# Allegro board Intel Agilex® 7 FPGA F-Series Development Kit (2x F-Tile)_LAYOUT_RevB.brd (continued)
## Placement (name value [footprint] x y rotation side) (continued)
C1024  0.1uF  [0402]  10.93 31.7 270 bottom
C1025  0.1uF  [0402]  5.6 31.7 270 bottom
C1026  0.1uF  [0402]  59.76 96.47 90 bottom
C1027  0.1uF  [0402]  61.09 57.48 180 top
C1028  0.1uF  [0402]  60.08 57.48 180 top
C1029  0.1uF  [0402]  63.13 57.48 180 top
C1030  0.1uF  [0402]  62.11 57.48 180 top
C1031  0.1uF  [0402]  68.08 39.64 180 top
C1032  100uF  [0805]  115.2 87.33 90 top
C1033  100uF  [0805]  122.05 87.33 90 top
C1034  100uF  [0805]  86.44 87.33 90 top
C1035  100uF  [0805]  125.99 87.33 90 top
C1036  100uF  [0805]  120.63 36.02 0 top
C1037  100uF  [0805]  114.94 36.02 0 top
C1038  47uF  [0603]  132.98 75.77 0 top
C1039  47uF  [0603]  133.36 56.09 0 top
C1040  47uF  [0603]  133.36 64.72 0 top
C1041  47uF  [0603]  133.36 44.53 0 top
C1042  10uF  [0402]  107.73 53.41 120 bottom
C1043  10uF  [0402]  107.7 51.55 120 bottom
C1044  22uF  [0603]  117.91 36.09 90 top
C1045  47uF  [0805]  70.11 70.18 270 top
C1046  47uF  [0805]  70.11 72.34 270 top
C1047  1uF  [0201]  94.1 71.3 210 bottom
C1048  1uF  [0201]  94.1 70.38 210 bottom
C1049  4.7uF  [0402]  104.02 71.14 0 bottom
C1050  4.7uF  [0402]  90.56 67.96 180 bottom
C1051  4.7uF  [0402]  89.54 72.69 60 bottom
C1052  4.7uF  [0402]  111.61 54.86 320 bottom
C1053  4.7uF  [0402]  111.46 53.15 180 bottom
C1054  4.7uF  [0402]  96.58 71.81 120 bottom
C1055  4.7uF  [0402]  96.58 70.89 120 bottom
C1056  4.7uF  [0402]  98.17 72.29 60 bottom
C1057  4.7uF  [0402]  108.55 71.37 300 bottom
C1058  4.7uF  [0402]  106.96 71.37 300 bottom
C1059  4.7uF  [0402]  105.34 71.49 300 bottom
C1060  4.7uF  [0402]  98.17 71.37 60 bottom
C1061  4.7uF  [0402]  92.64 69.99 240 bottom
C1062  4.7uF  [0402]  106.93 52.03 300 bottom
C1063  4.7uF  [0402]  94.21 52.97 300 bottom
C1064  4.7uF  [0402]  94.98 52.49 120 bottom
C1065  4.7uF  [0402]  93.39 51.57 120 bottom
C1066  4.7uF  [0402]  104.54 51.57 120 bottom
C1067  4.7uF  [0402]  104.54 52.49 120 bottom
C1068  4.7uF  [0402]  106.14 52.49 120 bottom
C1069  4.7uF  [0402]  94.98 51.57 120 bottom
C1070  10uF  [0402]  87.92 66.81 120 bottom
C1071  10uF  [0402]  85.34 67.16 300 bottom
C1072  1uF  [0201]  87.84 64.93 30 bottom
C1073  4.7uF  [0402]  113.72 59.15 180 bottom
C1074  47uF  [0805]  127.64 59.51 270 top
C1075  47uF  [0805]  127.64 65.74 270 top
C1076  47uF  [0805]  73.92 65.36 90 top
C1077  47uF  [0805]  70.11 60.53 90 top
C1078  47uF  [0805]  73.92 67.77 90 top
C1079  47uF  [0805]  82.71 87.33 270 top
C1080  0.1uF  [0402]  55.38 90.63 90 bottom
C1081  0.1uF  [0402]  53.47 87.45 0 bottom
C1082  2.2uF  [0402]  50.3 89.11 0 bottom
C1084  22uF  [1206]  42.81 84.91 90 top
C1085  22uF  [1206]  57.79 84.91 270 top
C1086  22uF  [1206]  40.27 84.91 90 top
C1087  22uF  [1206]  60.33 84.91 270 top
C1091  150uF  [2917_2MM]  42.81 81.1 270 bottom
C1092  4.7uF  [0603]  55.13 89.36 180 bottom
C1093  0.1uF, DNI  [0402]  198.13 59.01 0 bottom
C1096  22uF  [1206]  198 49.35 180 bottom
C1097  22uF  [1206]  198 46.81 180 top
C1098  1uF  [0402]  197.87 49.94 90 top
C1099  22uF  [1206]  193.17 49.35 0 bottom
C1100  22uF  [1206]  193.17 49.35 0 top
C1101  22uF  [1206]  193.17 46.81 0 bottom
C1102  22uF  [1206]  193.17 46.81 0 top
C1103  10nF  [0402]  194.32 59.01 180 bottom
C1105  100uF  [1206]  192.67 36.02 90 top
C1106  100uF  [1206]  192.67 36.02 90 bottom
C1107  100uF  [1206]  185.43 36.02 90 bottom
C1110  100uF  [1206]  170.31 35.89 90 bottom
C1111  100uF  [1206]  170.31 35.89 90 top
C1112  100uF  [1206]  175.14 35.89 90 bottom
C1115  22uF  [1206]  187.97 22.18 0 bottom
C1116  22uF  [1206]  187.97 19.51 0 top
C1117  22uF  [1206]  175.01 19.51 180 top
C1118  22uF  [1206]  175.01 22.18 180 bottom
C1120  1uF  [0402]  187.97 21.29 270 top
C1121  1uF  [0402]  175.01 21.29 90 top
C1122  100uF  [2917_4P3MM]  194.57 24.59 90 top
C1123  4.7uF  [0402]  179.65 30.69 90 bottom
C1124  10nF  [0402]  180.86 34.5 90 bottom
C1125  DNI  [0402]  183.27 35.77 90 bottom
C1126  220pF  [0402]  178.95 35 0 bottom
C1127  1uF  [0402]  50.76 87.71 270 bottom
C1128  47uF, DNI  [1206]  58.94 73.48 180 bottom
C1129  47uF, DNI  [1206]  53.73 73.48 0 bottom
C1132  100uF  [1206]  58.94 68.15 180 top
C1133  100uF  [1206]  58.94 70.94 180 top
C1134  100uF  [1206]  53.73 68.15 0 top
C1135  100uF  [1206]  53.73 70.94 0 top
C1136  470uF  [2917]  55.76 69.42 180 bottom
C1138  47uF, DNI  [1206]  47.89 73.48 180 bottom
C1139  47uF, DNI  [1206]  41.92 73.48 0 bottom
C1142  100uF  [1206]  42.17 68.15 0 top
C1143  100uF  [1206]  48.39 68.15 180 top
C1144  100uF  [1206]  42.17 70.94 0 top
C1145  100uF  [1206]  48.39 70.94 180 top
C1146  470uF  [2917]  46.24 69.42 0 bottom
C1149  2.2nF  [0402]  51.19 89.11 0 bottom
C1154  4.7uF  [0603]  197.11 72.98 90 bottom
C1156  2.2uF  [0402]  196.86 77.8 270 bottom
C1157  1uF  [0402]  195.46 77.35 180 bottom
C1158  0.1uF  [0402]  198.38 72.72 0 bottom
C1159  22uF  [1206]  192.67 85.3 0 top
C1160  22uF  [1206]  192.67 87.84 0 top
C1161  22uF  [1206]  194.19 67.77 180 top
C1162  22uF  [1206]  194.19 70.31 180 top
C1164  1uF  [0402]  192.41 76.53 0 bottom
C1165  1uF  [0402]  192.41 80.6 0 bottom
C1166  47uF, DNI  [1206]  171.71 68.28 90 top
C1167  47uF, DNI  [1206]  171.71 74.37 270 top
C1170  100uF  [1206]  174.38 68.28 90 top
C1171  100uF  [1206]  176.92 68.28 90 top
C1172  100uF  [1206]  174.38 74.37 270 top
C1173  100uF  [1206]  176.92 74.37 270 top
C1174  470uF  [2917]  179.08 71.96 0 bottom
C1176  150uF  [2917_2MM]  188.86 85.68 180 bottom
C1178  22pF  [0402]  200.16 76.15 270 bottom
C1179  2.2nF  [0402]  198.46 76.15 90 bottom
C1180  0.1uF  [0402]  195.21 74.63 270 bottom
C1181  47uF, DNI  [1206]  171.71 79.71 90 top
C1182  47uF, DNI  [1206]  171.71 87.45 270 top
C1185  100uF  [1206]  174.38 87.45 270 top
C1186  100uF  [1206]  174.38 79.71 90 top
C1187  100uF  [1206]  176.92 87.45 270 top
C1188  100uF  [1206]  176.92 79.71 90 top
C1189  470uF  [2917]  179.08 85.68 0 bottom
C1191  22pF  [0402]  196.86 78.69 270 bottom
C1193  2.2nF  [0402]  196.86 76.91 270 bottom
C1194  0.1uF  [0402]  66.05 39.64 180 top
C1195  10nF  [0402]  69.1 39.7 180 top
C1196  10nF  [0402]  67.06 39.64 180 top
C1197  10uF  [0402]  64.9 39.64 0 top
C1198  47uF  [0603]  63.51 37.8 180 top
C1199  1nF, DNI  [0402]  73.67 44.15 180 bottom
C1200  DNI  [0402]  193.05 58.94 0 bottom
C1201  DNI  [0402]  189.87 56.66 0 top
C1202  100pf  [0402]  189.87 54.88 180 top
C1203  0.1uF  [0402]  197.43 54.69 90 bottom
C1204  2.2uF  [0402]  198.13 52.91 0 bottom
C1205  0.1uF  [0402]  51.57 84.66 90 bottom
C1206  0.1uF  [0402]  47.51 84.66 90 bottom
C1207  2.2uF  [0402]  47.76 87.45 180 bottom
C1208  4.7uF  [0603]  55.89 86.95 270 bottom
C1209  22pF  [0402]  51.95 92.41 0 bottom
C1210  22pF  [0402]  49.41 89.11 0 bottom
C1211  2.2nF  [0402]  51.95 90.71 180 bottom
C1212  220nF  [0402]  51.06 91.51 0 bottom
C1213  220nF  [0402]  52.84 91.52 180 bottom
C1214  220nF  [0402]  199.26 77.04 270 bottom
C1215  220nF  [0402]  199.27 75.26 90 bottom
C1216  4.7uF  [0603]  194.7 72.21 180 bottom
C1217  2.2uF  [0402]  195.21 80.34 90 bottom
C1218  1uF, DNI  [0402]  180.6 29.8 315 bottom
C1219  1uF  [0402]  180.09 59.51 180 top
C1220  10nF  [0402]  58.3 77.17 90 top
C1221  10nF  [0402]  42.3 77.17 90 top
C1222  10nF  [0402]  184.54 70.82 0 top
C1223  10nF  [0402]  183.4 86.69 0 top
C1224  1uF  [0201]  97.42 57.89 0 bottom
C1225  0.1uF  [0402]  85.35 17.6 270 bottom
C1226  0.1uF  [0402]  85.35 15.19 270 bottom
C1227  0.1uF  [0402]  71.38 20.53 0 bottom
C1228  0.1uF  [0402]  85.35 19.89 270 bottom
C1229  0.1uF  [0402]  81.16 13.29 180 bottom
C1230  0.1uF  [0402]  79.89 13.29 180 bottom
C1231  0.1uF  [0402]  78.62 13.29 180 bottom
C1232  0.1uF  [0402]  77.35 13.29 180 bottom
C1233  0.1uF  [0402]  70.87 13.29 180 bottom
C1234  0.1uF  [0402]  75.45 13.29 180 bottom
C1235  0.1uF  [0402]  72.4 13.29 180 bottom
C1236  0.1uF  [0402]  71.38 22.94 0 bottom
C1237  0.1uF  [0402]  91.87 69.51 60 bottom
C1238  100uF  [1206]  130.18 77.68 180 bottom
C1239  100uF  [1206]  130.18 69.93 180 bottom
C1240  100uF  [1206]  130.18 67.52 180 bottom
C1241  100uF  [1206]  130.18 65.1 180 bottom
C1242  100uF  [1206]  130.18 62.69 180 bottom
C1243  100uF  [1206]  130.18 60.28 180 bottom
C1244  100uF  [1206]  130.18 57.74 180 bottom
C1245  100uF  [1206]  130.18 55.32 180 bottom
C1246  100uF  [1206]  130.18 52.91 180 bottom
C1247  100uF  [1206]  130.18 50.5 180 bottom
C1248  100uF  [1206]  130.18 47.96 180 bottom
C1249  100uF  [1206]  135.14 43.13 180 bottom
C1250  100uF  [1206]  135.14 62.69 180 bottom
C1251  100uF  [1206]  117.36 36.27 270 bottom
C1252  100uF  [1206]  135.14 57.74 180 bottom
C1253  100uF  [1206]  135.14 52.91 180 bottom
C1254  100uF  [1206]  123.45 36.15 270 bottom
C1255  100uF  [1206]  135.14 47.96 180 bottom
C1256  100uF  [1206]  124.04 87.96 180 bottom
C1257  100uF  [1206]  129.04 87.96 180 bottom
C1258  220uF  [1210]  129.17 36.02 270 top
C1259  220uF  [1210]  130.69 87.96 0 top
C1260  10uF  [0402]  108.14 66.05 0 bottom
C1261  10uF  [0402]  95.39 67 180 bottom
C1262  10uF  [0402]  93.8 56.88 180 bottom
C1263  10uF  [0402]  106.55 55.98 0 bottom
C1264  10uF  [0402]  98.17 54.81 240 bottom
C1265  10uF  [0402]  95.81 53.89 120 bottom
C1266  10uF  [0402]  98.99 56.65 120 bottom
C1267  10uF  [0402]  102.72 55.42 0 bottom
C1268  10uF  [0402]  104.96 55.96 180 bottom
C1269  10uF  [0402]  109.74 65.13 0 bottom
C1270  10uF  [0402]  108.14 59.64 180 bottom
C1271  10uF  [0402]  109.74 55.96 180 bottom
C1272  10uF  [0402]  108.14 56.88 180 bottom
C1273  10uF  [0402]  109.74 58.72 180 bottom
C1274  10uF  [0402]  109.74 62.37 0 bottom
C1275  10uF  [0402]  108.14 63.29 0 bottom
C1276  10uF  [0402]  92.21 66.97 0 bottom
C1277  10uF  [0402]  93.8 67.92 180 bottom
C1278  10uF  [0402]  93.8 65.16 180 bottom
C1279  10uF  [0402]  93.8 60.53 0 bottom
C1280  10uF  [0402]  92.21 58.69 0 bottom
C1281  10uF  [0402]  92.21 61.45 0 bottom
C1282  10uF  [0402]  91.82 55.27 120 bottom
C1283  10uF  [0402]  105.34 70.57 120 bottom
C1284  10uF  [0402]  100.82 69.35 180 bottom
C1285  10uF  [0402]  109.61 67.89 0 bottom
C1286  10uF  [0402]  106.55 66.97 0 bottom
C1287  10uF  [0402]  104.16 67.41 180 bottom
C1288  10uF  [0402]  98.58 68.81 0 bottom
C1289  10uF  [0402]  95.39 69.76 180 bottom
COUT1  100uF  [1206]  147.2 48.47 0 bottom
COUT2  100uF  [1206]  147.2 45.93 0 bottom
COUT3  100uF  [1206]  147.2 43.39 0 bottom
COUT4  100uF  [1206]  147.2 40.85 0 bottom
COUT5  100uF  [1206]  147.2 38.31 0 bottom
COUT6  100uF  [1206]  147.2 35.89 0 bottom
COUT7  220uF  [1210]  147.96 48.08 0 top
COUT8  220uF, DNI  [1206]  135.14 55.32 180 bottom
COUT9  100uF  [1206]  147.2 62.94 0 bottom
COUT10  100uF  [1206]  147.2 60.53 0 bottom
COUT11  100uF  [1206]  147.2 58.12 0 bottom
COUT12  100uF  [1206]  147.2 55.7 0 bottom
COUT13  220uF  [1210]  147.96 62.56 0 top
COUT14  220uF, DNI  [1206]  135.14 45.54 180 bottom
COUT15  100uF  [1206]  147.2 53.29 0 bottom
COUT16  100uF  [1206]  147.2 50.88 0 bottom
COUT17  100uF  [1206]  147.2 77.42 0 bottom
COUT18  100uF  [1206]  147.2 75.01 0 bottom
COUT19  220uF  [1210]  147.96 77.04 0 top
COUT20  220uF, DNI  [1206]  135.14 65.1 180 bottom
COUT21  100uF  [1206]  147.2 72.6 0 bottom
COUT22  100uF  [1206]  147.2 70.18 0 bottom
COUT23  100uF  [1206]  147.2 67.77 0 bottom
COUT24  100uF  [1206]  147.2 65.36 0 bottom
COUT25  100uF  [1206]  147.2 91.9 0 bottom
COUT26  100uF  [1206]  147.2 84.66 0 bottom
COUT27  100uF  [1206]  147.2 89.49 0 bottom
COUT28  100uF  [1206]  147.2 87.07 0 bottom
COUT29  100uF  [1206]  147.2 79.83 0 bottom
COUT30  100uF  [1206]  147.2 82.25 0 bottom
COUT31  220uF  [1210]  147.96 90.38 0 top
COUT32  220uF, DNI  [1206]  135.52 74.75 180 bottom
COUT33  100uF  [1206]  147.2 32.97 0 bottom
COUT34  100uF  [1206]  147.2 30.56 0 bottom
COUT35  100uF  [1206]  147.2 28.15 0 bottom
COUT36  100uF  [1206]  147.2 25.73 0 bottom
COUT37  100uF  [1206]  147.2 23.32 0 bottom
COUT39  220uF  [1210]  147.84 32.34 0 top
D1  GREEN_LED  [LED_0603]  40.39 108.41 270 top
D2  BLUE LED  [LED_0603]  38.49 108.41 270 top
D3  YELLOW_LED  [LED_0603]  64.65 28.3 180 top
D4  YELLOW_LED  [LED_0603]  53.5 50.05 180 top
D5  RED_LED  [LED_0603]  36.65 108.41 270 top
D6  GREEN_LED  [LED_0603]  64.65 24.87 180 top
D7  GREEN_LED  [LED_0603]  53.5 46.64 180 top
D8  GREEN_LED  [LED_0603]  242.65 106.28 270 top
D9  GREEN_LED  [LED_0603]  239.35 106.28 270 top
D10  GREEN_LED  [LED_0603]  236.05 106.28 270 top
D11  GREEN_LED  [LED_0603]  232.75 106.28 270 top
D12  GREEN_LED  [LED_0603]  34.81 108.41 270 top
D13  5p0SMDJ12A  [TVS_5P0SMDJ12A]  229.12 37.54 180 bottom
D14  STPS30L30DJF-TR  [POWERFLAT_5X6]  225.81 52.15 90 top
D15  5p0SMDJ12A  [TVS_5P0SMDJ12A]  226.7 94.69 0 bottom
D16  STPS30L30DJF-TR  [POWERFLAT_5X6]  221.75 72.72 0 bottom
D17  FDLL4148  [SOD-80]  232.54 27.51 270 top
D18  CMDSH-3  [SOD323]  57.92 90.88 270 bottom
D19  CMDSH-3  [SOD323]  57.92 86.82 90 bottom
D20  CMDSH-3  [SOD323]  198.64 70.18 180 bottom
D21  CMDSH-3  [SOD323]  194.57 70.18 0 bottom
D22  FDLL4148  [SOD-80]  203.51 106.38 180 bottom
D23  FDLL4148  [SOD-80]  203.51 103.96 180 bottom
D24  GREEN_LED  [LED_0603]  35.31 62.18 270 top
D25  GREEN_LED  [LED_0603]  29.09 62.05 270 top
D26  BAT54  [SOT-23-3]  223.4 64.47 180 bottom
D27  BAT54  [SOT-23-3]  223.4 64.47 0 top
D28  LT1389  [S8]  218.32 62.05 180 bottom
EU1  MAX31730ATC+  [LCC12_S30_50DF25X17MA]  64.55 80.88 0 top
EU2  MAX31730ATC+  [LCC12_S30_50DF25X17MA]  91.93 35.49 270 top
FB1  220ohm, .6Amax, 0.18DCR  [0402]  21.67 85.52 90 bottom
FB2  220ohm, .6Amax, 0.18DCR  [0402]  82.18 37.6 180 top
FB3  120ohm, 800mA  [805]  75.06 76.91 180 bottom
FB4  22ohm@100Mhz 8A  [0603]  70.49 75.9 90 bottom
FB5  22ohm@100Mhz 8A  [0603]  72.27 51.77 270 bottom
FB6  22ohm@100Mhz 8A  [0603]  100.08 36.02 270 top
FB7  0.1uH, 19A  [SL1616A-R10MHF]  80.78 33.35 270 top
FB8  22ohm@100Mhz 8A  [0603]  98.56 36.02 270 top
FB9  80ohm @ 100Mhz  [0805]  36.71 43.51 90 bottom
FB10  80ohm @ 100Mhz  [0805]  36.71 48.21 90 bottom
FB11  80ohm @ 100Mhz  [0805]  36.71 52.28 90 bottom
FB12  22ohm@100Mhz 8A  [0603]  72.27 44.4 270 bottom
FB13  22ohm@100Mhz 8A  [0603]  58.55 43.51 270 bottom
FB14  22ohm@100Mhz 8A  [0603]  61.09 43.51 270 bottom
FB15  22ohm@100Mhz 8A  [0603]  63.63 43.51 270 bottom
FB16  22ohm@100Mhz 8A  [0603]  54.87 46.81 270 bottom
FB17  22ohm@100Mhz 8A  [0603]  54.87 50.75 90 bottom
FB18  22ohm@100Mhz 8A  [0603]  70.75 58.5 90 bottom
FB19  22ohm@100Mhz 8A  [0603]  65.29 43.51 270 bottom
FB20  22ohm@100Mhz 8A  [0603]  54.62 57.61 90 bottom
FB21  22ohm@100Mhz 8A  [0603]  67.83 43.51 270 bottom
FB22  22ohm@100Mhz 8A  [0603]  68.08 55.32 90 bottom
FB23  22ohm@100Mhz 8A  [0603]  65.54 55.32 90 bottom
FB24  22ohm@100Mhz 8A  [0603]  63 55.32 90 bottom
FB25  22ohm@100Mhz 8A  [0603]  60.46 55.32 90 bottom
FB26  22ohm@100Mhz 8A  [0603]  58.81 55.32 90 bottom
FB27  220ohm, .6Amax, 0.18DCR  [0402]  12.71 54.69 90 bottom
FB28  220ohm, .6Amax, 0.18DCR  [0402]  15.63 32.08 270 bottom
FB29  220ohm, .6Amax, 0.18DCR  [0402]  25.15 52.78 90 bottom
FB30  600 Ohm, 0.5A, 0.35DCR  [0603]  14.36 100.28 90 top
FB37  220ohm, .6Amax, 0.18DCR  [0402]  6.1 41.35 270 bottom
FB38  220ohm, .6Amax, 0.18DCR  [0402]  4.33 41.35 270 bottom
FB39  220ohm, .6Amax, 0.18DCR  [0402]  12.71 44.66 90 bottom
FB40  220ohm, .6Amax, 0.18DCR  [0402]  12.71 52.66 90 bottom
FB41  80ohm @ 100Mhz  [0805]  64.4 34.62 180 top
FB42  DNI  [0603]  57.79 44.27 180 bottom
J1  PCIE_Slot  [PCIX-16PORT]  45.65 4.1 0 top
J2  FAN_Conn  [MOLEX_0470533000]  237.5 15.19 270 top
J3  MOLEX 70247-1051  [MOLEX_70247-1051]  17.15 100.66 0 top
J4  DDR4x72x288  [DDR4DIMM_SMT]  113.42 96.98 0 top
J5  DDR4x72x288  [DDR4DIMM_SMT]  113.42 104.6 0 top
J6  QSH-030-01-F-D-A  [QSH-030-01-C-D-A]  210.07 24.72 180 top
J7  -  [UE36-A1015-2000T]  47.41 26.56 0 top
J8  -  [FS1-K38-20ZA-A0]  40.55 48.35 270 top
J9  -  [G97R12322HR]  6.03 74.63 0 top
J10  MICRO_USB_CONN  [MOLEX-MICRO-USB-47589-001]  1.45 95.74 90 top
J11  PCIe 2x4 ATX  [MOLEX_455860005]  240.11 90.19 270 top
J12  1x3_HDR_TH  [1X3_HDR_TH]  245.63 70.56 0 top
J13  DF3-4P-2DSA  [DF3-4P-2DSA_01]  239.15 33.35 180 top
J14  SMA  [SMA_LTI-SASF546-P26-X1]  248.42 61.93 0 top
J15  SMA  [SMA_LTI-SASF546-P26-X1]  248.42 26.37 0 top
J105  CON2  [HDR2X1_100MIL]  50.55 64.34 0 top
J106  CON2  [HDR2X1_100MIL]  42.93 64.34 0 top
J107  DF3-4P-2DSA  [DF3-4P-2DSA_01]  197.75 99.68 0 top
L1  1uH  [IFSC1008ABER1R0M01]  47.66 24.36 0 bottom
L2  1uH  [IFSC1008ABER1R0M01]  47.66 30.46 0 bottom
L3  1uH  [IFSC1008ABER1R0M01]  47.66 33.51 0 bottom
L5  72nH  [EATON_FP0805R1-R07-R]  148.27 40.85 270 top
L6  72nH  [EATON_FP0805R1-R07-R]  148.27 55.32 270 top
L7  72nH  [EATON_FP0805R1-R07-R]  148.27 69.8 270 top
L8  72nH  [EATON_FP0805R1-R07-R]  148.27 84.28 270 top
L9  72nH  [EATON_FP0805R1-R07-R]  148.27 26.37 270 top
L10  0.33uH  [XAL5030]  53.73 76.07 270 top
L11  0.33uH  [XAL5030]  46.87 76.07 270 top
L12  0.47uH  [XEL4030]  183.14 74.5 180 top
L13  0.33uH  [XAL6030]  182.51 81.74 180 top
MTH1  MT_HOLE_GND  [MH_D125C175T_TB315]  7.5 104.65 0 top
MTH2  MT_HOLE_GND  [MH_D125C175T_TB315]  249.03 106.14 0 top
MTH3  MT_HOLE_GND  [MH_PTH_3_8MM]  70.75 86.59 0 top
MTH4  MT_HOLE_GND  [MTH250R125]  210.07 85.49 0 top
MTH5  MT_HOLE_GND  [MH_PTH_3_8MM]  138.82 33.25 0 top
MTH6  MT_HOLE_GND  [MTH250R125]  187.21 64.67 0 top
MTH7  MT_HOLE_GND  [MH_D125C175T_TB315]  249.01 16.65 0 top
MTH8  MT_HOLE_GND  [MH_D125C175T_TB315]  7.5 9.35 0 top
MTH9  MT_HOLE_GND  [MH_PTH_3_8MM]  70.75 33.25 0 top
MTH10  MT_HOLE_GND  [MH_PTH_3_8MM]  138.82 86.59 0 top
MTH11  MT_HOLE_GND  [MTH250R125]  232.93 64.67 0 top
NOREF  -  []  45 0.5 0 top
NOREF#2  -  []  45.5 0 0 top
NOREF#3  -  []  143.35 2.95 0 top
NOREF#4  -  []  15 4.5 0 top
NOREF#5  -  []  7.5 94.75 0 top
NOREF#6  -  []  7.5 9.35 0 top
NOREF#7  -  []  144.74 5.32 0 top
NOREF#8  -  []  7.5 94.75 0 top
NOREF#9  -  [unnamed#2]  244.02 20.53 0 top
NOREF#10  -  []  15 12.75 0 top
NOREF#11  -  []  139.03 11 0 top
NOREF#12  -  []  0 4.5 0 top
NOREF#13  -  []  129.3 0.5 0 top
NOREF#14  -  []  56.2 7.45 0 top
NOREF#15  -  []  7.5 9.35 0 top
NOREF#16  -  []  7.5 104.88 0 top
NOREF#17  -  []  33.35 4.5 0 top
NOREF#18  -  [unnamed#2]  3.64 13.74 0 top
NOREF#19  -  [unnamed#3]  64.27 9.07 0 top
NOREF#20  -  []  58.1 0.5 0 top
NOREF#21  -  []  60.08 -68.63 0 top
NOREF#22  -  []  0 111.15 0 top
NOREF#23  -  []  58.29 0.31 0 top
NOREF#24  -  [unnamed#2]  88.27 9.19 0 top
NOREF#25  -  []  147.3 10.21 0 top
NOREF#26  -  []  56.2 0.5 0 top
NOREF#27  -  [unnamed#2]  82.18 9.19 0 top
NOREF#28  -  []  -309.9 -46.1 0 top
NOREF#29  -  []  7.75 113.69 0 top
NOREF#30  -  []  7.5 94.75 0 top
NOREF#31  -  []  132.04 3.45 0 top
NOREF#32  -  []  7.5 104.88 0 top
NOREF#33  -  []  254 12.75 0 top
NOREF#34  -  []  0.01 123.85 0 top
NOREF#35  -  [unnamed#2]  2.85 108.26 0 top
NOREF#36  -  [unnamed#2]  70.24 9.07 0 top
NOREF#37  -  [unnamed#3]  100.59 9.07 0 top
NOREF#38  -  []  0 4.5 0 top
NOREF#39  -  []  41.35 10.92 0 top
NOREF#40  -  []  113.52 13.16 0 top
NOREF#41  -  []  7.5 9.35 0 top
NOREF#42  -  []  41.35 10.92 0 top
NOREF#43  -  [unnamed#2]  242.02 19.33 180 bottom
NOREF#44  -  [unnamed#2]  2.85 108.26 180 bottom
NOREF#45  -  [unnamed#2]  4.22 16.21 180 bottom
Q1  FDV305N  [SOT23]  24.14 88.47 180 bottom
Q2  MMBT3906  [SC75_SOT416]  20.84 61.17 90 top
Q3  MMBT3906  [SC75_SOT416]  238.51 47.96 270 top
Q4  FDV305N  [SOT23]  16.9 83.9 180 bottom
Q7  FDV305N  [SOT23]  237.37 102.82 180 bottom
Q8  FDV305N  [SOT23]  12.33 18.11 90 bottom
Q9  FDV305N  [SOT23]  21.19 18.11 90 bottom
Q10  FDV305N  [SOT23]  16.14 34.83 180 bottom
Q11  FDV305N  [SOT23]  12.83 39.83 180 bottom
Q12  FDV305N  [SOT23]  233.31 102.82 180 bottom
Q13  FDV305N  [SOT23]  229.5 102.82 180 bottom
Q14  FDV305N  [SOT23]  225.69 102.82 180 bottom
Q15  FDV305N  [SOT23]  13.09 83.9 180 bottom
Q16  PSMN1R0-30YLD  [NFET_PSMN1R0-30YLD]  217.05 74.63 90 top
Q17  SI2302CDS-T1-GE3  [SOT23]  216.29 80.09 270 bottom
Q18  PSMN1R0-30YLC,115  [POWER-SO8]  38.74 100.25 180 top
Q19  FDV305N  [SOT23]  32.27 61.67 270 top
Q20  FDV305N  [SOT23]  26.17 61.67 270 top
Q21  MMBT3906  [SC75_SOT416]  58.81 78.82 270 top
Q22  MMBT3906  [SC75_SOT416]  41.79 78.82 270 top
Q23  MMBT3906  [SC75_SOT416]  186.06 70.31 180 top
Q24  MMBT3906  [SC75_SOT416]  185.05 87.2 180 top
R1  4.70K, DNI  [0402]  49.41 11 180 top
R2  4.70K, DNI  [0402]  52.46 11 180 top
R3  100K  [0402]  50.3 11 0 top
R4  100K  [0402]  51.44 11 0 top
R5  10.0K  [0402]  53.6 11 180 top
R6  10.0K  [0402]  56.52 11 180 bottom
R7  10.0K, DNI  [0402]  54.49 11 180 top
R8  10.0K  [0402]  55.51 11 180 top
R12  100K  [0402]  73.29 11.66 90 top
R13  49.9  [0402]  58.17 11 0 top
R14  49.9  [0402]  65.92 11 180 bottom
R15  49.9  [0402]  75.06 11.66 90 top
R16  49.9  [0402]  78.75 11 180 bottom
R17  49.9  [0402]  80.53 11 180 bottom
R18  49.9  [0402]  126.88 11 0 top
R19  49.9  [0402]  96.53 11 180 bottom
R20  49.9  [0402]  60.33 11 0 top
R21  49.9  [0402]  78.87 11 0 top
R22  49.9  [0402]  96.78 11 0 top
R23  49.9  [0402]  122.82 11 0 top
R24  10.0K, DNI  [0402]  34.17 25.61 0 bottom
R25  10.0K, DNI  [0402]  34.17 23.7 0 bottom
R26  10.0K, DNI  [0402]  34.55 19.64 90 bottom
R27  10.0K, DNI  [0402]  43.82 20.4 270 bottom
R28  10.0K  [0402]  43.57 21.92 180 bottom
R29  10.0K  [0402]  34.55 20.53 270 bottom
R30  10.0K  [0402]  34.17 27.51 180 bottom
R31  10.0K  [0402]  34.17 21.92 0 bottom
R32  10.0K  [0402]  36.32 91.26 270 bottom
R33  10.0K  [0402]  37.72 91.66 0 bottom
R34  10.0K  [0402]  28.7 91.26 270 bottom
R35  10.0K  [0402]  26.8 89.11 180 bottom
R36  10.0K  [0402]  24.32 91.26 90 bottom
R37  10.0K  [0402]  28.7 93.26 270 bottom
R38  10.0K  [0402]  31.92 91.26 90 bottom
R39  10.0K  [0402]  36.32 93.26 270 bottom
R40  4.70K  [0402]  33.94 67.39 180 bottom
R41  4.70K  [0402]  35.31 70.56 270 bottom
R42  4.70K  [0402]  37.35 74.12 270 bottom
R43  4.70K  [0402]  35.31 75.39 270 bottom
R52  33.2  [0402]  25.18 85.05 0 bottom
R53  33.2  [0402]  20.2 85.03 0 bottom
R54  33.2  [0402]  35.69 83.64 270 bottom
R55  10.0K  [0402]  27.18 85.05 0 bottom
R56  4.70K, DNI  [0402]  33.03 67.39 0 bottom
R57  4.70K, DNI  [0402]  35.31 71.58 90 bottom
R58  4.70K, DNI  [0402]  37.35 73.23 90 bottom
R59  4.70K, DNI  [0402]  35.31 74.12 90 bottom
R69  0  [0402]  23.76 66.25 0 bottom
R70  0  [0402]  24.82 66.25 0 bottom
R71  33.2  [0402]  25.79 66.25 180 bottom
R72  10.0K  [0402]  35.31 73.1 90 bottom
R73  10.0K  [0402]  31.88 67.39 0 bottom
R74  10.0K  [0402]  30.49 67.01 90 bottom
R75  10.0K  [0402]  26.8 66.25 0 bottom
R76  10.0K  [0402]  37.35 75.39 90 bottom
R77  10.0K, DNI  [0402]  37.35 78.69 90 bottom
R78  10.0K  [0402]  37.35 77.68 270 bottom
R79  33.2  [0402]  35.31 76.53 270 bottom
R80  10.0K  [0402]  37.35 79.71 270 bottom
R81  10.0K  [0402]  26.8 87.33 0 bottom
R82  56.2  [0402]  40.39 108.41 180 bottom
R83  1.00K  [0402]  18.93 107.14 180 bottom
R84  1.00K  [0402]  20.96 107.14 180 bottom
R85  1.00K  [0402]  30.49 105.23 180 bottom
R86  1.00K  [0402]  19.95 107.14 0 bottom
R87  10.0K  [0402]  203.21 101.81 180 bottom
R88  0  [0402]  17.91 107.14 0 bottom
R89  0  [0402]  233.05 18.37 0 top
R90  0, DNI  [0402]  204.22 101.81 0 bottom
R91  10.0K  [0402]  233.05 22.68 180 top
R92  10.0K  [0402]  233.05 16.46 0 top
R93  10  [0402]  14.83 74.5 90 top
R94  1.00K  [0402]  16.9 107.14 0 bottom
R95  10.0K  [0402]  68.35 78.36 90 bottom
R96  10.0K  [0402]  68.35 76.36 90 bottom
R97  10.0K  [0402]  250.71 49.86 90 bottom
R98  10.0K  [0402]  250.71 51.13 90 bottom
R99  1.00K  [0402]  244.61 49.86 90 bottom
R100  1.00K  [0402]  244.61 51.13 90 bottom
R101  1.00K  [0402]  244.61 52.4 90 bottom
R102  1.00K  [0402]  244.61 53.67 90 bottom
R103  33.2  [0402]  71.44 64.38 90 bottom
R104  2K  [0402]  82.89 70.67 0 bottom
R105  10.0K  [0402]  32.9 59.13 0 bottom
R106  10.0K  [0402]  31.88 59.13 0 bottom
R107  10  [0402]  75.06 75.58 180 top
R108  240  [0402]  100.59 76.36 240 bottom
R109  240  [0402]  110.15 76.41 240 bottom
R110  240  [0402]  94.6 78.42 180 bottom
R114  240  [0402]  118.86 49.8 300 bottom
R115  49.9, DNI  [0402]  118.14 70.94 60 bottom
R116  49.9, DNI  [0402]  116.44 69.95 240 bottom
R117  49.9, DNI  [0402]  116.5 66.38 90 bottom
R118  49.9, DNI  [0402]  116.5 67.6 90 bottom
R119  10.0K  [0402]  130.56 75.52 270 bottom
R123  0  [0402]  59.76 97.74 270 bottom
R124  499  [0402]  117.38 68.92 120 bottom
R125  10.0K  [0402]  53.41 104.35 90 bottom
R126  10.0K  [0402]  59.89 104.73 90 bottom
R127  0  [0402]  59.89 105.74 270 bottom
R128  499  [0402]  84.6 55.78 120 bottom
R131  0  [1206]  49.95 95.71 0 bottom
R132  0  [1206]  49.95 98.25 0 bottom
R134  10.0K  [0402]  127.42 99.52 180 bottom
R135  10.0K  [0402]  120.66 93.55 180 bottom
R136  0  [0402]  172.91 95.06 90 bottom
R137  0  [0402]  172.86 93.98 270 bottom
R138  0  [0402]  134.68 100.21 90 bottom
R139  10.0K  [0402]  98.84 95.07 270 bottom
R140  0, DNI  [0402]  98.11 93.93 270 bottom
R141  0, DNI  [0402]  100.24 93.55 0 bottom
R142  0, DNI  [0402]  99.4 100.38 180 bottom
R143  10.0K  [0402]  103.59 99.49 180 bottom
R145  0  [0402]  176.69 99.52 0 bottom
R147  0  [1206]  49.95 103.33 0 bottom
R148  0  [1206]  49.95 105.87 0 bottom
R150  10.0K  [0402]  127.42 107.14 180 bottom
R151  10.0K  [0402]  120.15 101.68 90 bottom
R152  10.0K  [0402]  172.91 102.68 270 bottom
R153  0  [0402]  172.86 101.6 270 bottom
R154  0  [0402]  134.68 107.77 90 bottom
R155  10.0K  [0402]  98.84 102.69 270 bottom
R156  0, DNI  [0402]  98.11 101.55 270 bottom
R157  0, DNI  [0402]  100.24 101.17 0 bottom
R158  0, DNI  [0402]  99.4 108 180 bottom
R159  10.0K  [0402]  103.59 107.11 180 bottom
R161  0  [0402]  176.69 107.14 0 bottom
R163  240  [0402]  129.46 26.96 180 bottom
R164  240  [0402]  117.26 26.96 180 bottom
R165  240  [0402]  105.07 26.96 180 bottom
R166  240  [0402]  92.88 26.96 180 bottom
R167  36  [0402]  76.03 19.31 270 bottom
R168  36  [0402]  78.75 19.31 90 bottom
R169  36  [0402]  76.03 18.48 270 bottom
R170  36  [0402]  78.75 20.13 90 bottom
R171  36  [0402]  76.03 20.13 270 bottom
R172  36  [0402]  82.76 19.31 90 bottom
R173  240  [0402]  80.59 26.96 180 bottom
R174  36  [0402]  72.81 19.31 270 bottom
R175  36  [0402]  80.79 16.28 0 bottom
R176  36  [0402]  73.98 16.28 0 bottom
R177  36  [0402]  77.77 17.08 0 bottom
R178  36  [0402]  76.03 20.96 270 bottom
R179  36  [0402]  74.88 16.28 0 bottom
R180  36  [0402]  78.75 20.96 90 bottom
R181  36  [0402]  79.89 16.28 0 bottom
R182  36  [0402]  72.81 22.61 270 bottom
R183  36  [0402]  78.75 21.78 90 bottom
R184  36  [0402]  82.76 21.78 90 bottom
R186  36  [0402]  72.81 21.78 270 bottom
R187  36  [0402]  82.76 20.96 90 bottom
R188  36  [0402]  72.81 20.13 270 bottom
R189  36  [0402]  82.76 20.13 90 bottom
R190  36  [0402]  78.75 22.61 90 bottom
R191  36  [0402]  75.29 23.43 270 bottom
R192  36  [0402]  76.03 21.78 270 bottom
R193  36  [0402]  76.5 17.08 0 bottom
R194  1.00K  [0402]  82.76 18.48 90 bottom
R195  1.00K  [0402]  73.79 18.46 90 bottom
R196  1.00K, DNI  [0402]  73.64 17.63 90 bottom
R197  1.00K, DNI  [0402]  82.76 22.61 90 bottom
R198  1.00K, DNI  [0402]  76.59 24.43 180 bottom
R199  0  [0402]  82.81 23.9 0 bottom
R200  36  [0402]  77.49 24.43 180 bottom
R201  36  [0402]  76.03 22.61 90 bottom
R202  36  [0402]  78.39 24.43 180 bottom
R203  49.9, DNI  [0402]  209.82 21.1 90 bottom
R204  10.0K, DNI  [0402]  209.31 29.28 270 bottom
R205  10.0K, DNI  [0402]  208.92 22.2 90 bottom
R206  10.0K  [0402]  204.48 23.7 0 bottom
R207  10.0K  [0402]  204.48 27.76 0 bottom
R208  10.0K  [0402]  204.86 19.89 180 bottom
R209  10.0K  [0402]  205.49 24.84 180 bottom
R210  10.0K, DNI  [0402]  204.48 25.73 180 bottom
R211  10.0K  [0402]  34.81 29.39 0 bottom
R212  54.9K  [0402]  42.36 28.58 180 bottom
R213  27.4K  [0402]  42.36 31.56 0 bottom
R214  10.0K  [0402]  37.9 32.49 90 bottom
R215  4.70K  [0402]  44.97 22.43 90 bottom
R217  51.1K  [0402]  46.82 22.43 90 bottom
R218  51.1K  [0402]  46.82 21.44 90 bottom
R219  1M  [0402]  9.15 35.13 180 bottom
R220  10.0K  [0402]  25.15 41.35 270 bottom
R221  54.9K  [0402]  33.23 41.83 180 bottom
R222  27.4K  [0402]  33.23 44.81 0 bottom
R223  10.0K  [0402]  28.77 45.74 90 bottom
R224  1M  [0402]  7.12 57.36 180 bottom
R225  0  [0402]  13.38 79.97 90 top
R226  0  [0402]  13.38 79.08 90 top
R227  0, DNI  [0402]  6.7 69.04 180 bottom
R228  15.4K, DNI  [HC_R0201]  70.87 52.11 90 top
R229  15.4K, DNI  [HC_R0201]  70.87 53.7 270 top
R230  15.4K, DNI  [HC_R0201]  70.87 48.55 90 top
R231  15.4K, DNI  [HC_R0201]  70.87 50.14 270 top
R232  100  [0402]  73.51 52.91 0 top
R233  100  [0402]  73.51 49.35 0 top
R234  10.0K, DNI  [0402]  70.02 53.79 180 top
R235  10.0K, DNI  [0402]  70.02 48.46 0 top
R236  10.0K, DNI  [0402]  70.02 50.24 180 top
R237  10.0K, DNI  [0402]  70.02 52.01 0 top
R238  1.00K  [0402]  60.08 60.28 0 top
R239  1.00K  [0402]  58.55 49.48 90 bottom
R240  10  [0402]  56.65 50.24 90 top
R241  1.00K, DNI  [0402]  56.65 55.07 270 top
R242  1.00K, DNI  [0402]  58.17 40.72 0 top
R243  1.00K, DNI  [0402]  56.65 42.09 270 top
R244  1.00K, DNI  [0402]  56.65 45.21 270 top
R245  1.00K, DNI  [0402]  56.65 46.18 270 top
R246  1.00K, DNI  [0402]  56.65 49.23 270 top
R247  0  [0402]  64.4 41.86 180 top
R248  0  [0402]  63.38 41.86 180 top
R249  0  [0402]  66.43 41.86 180 top
R250  0  [0402]  65.41 41.86 180 top
R251  0  [0402]  68.46 41.86 180 top
R252  0  [0402]  67.44 41.86 180 top
R253  0  [0402]  60.33 41.86 180 top
R254  0  [0402]  59.32 41.86 180 top
R256  1.00K  [0402]  56.65 54.18 90 top
R257  1.00K  [0402]  56.65 53.29 90 top
R258  1.00K  [0402]  56.65 41.1 90 top
R259  1.00K  [0402]  56.65 43.18 90 top
R260  1.00K  [0402]  56.65 44.15 90 top
R261  1.00K  [0402]  56.65 47.2 90 top
R262  1.00K  [0402]  56.65 48.21 90 top
R263  4.70K  [0402]  56.65 51.51 270 top
R264  4.70K  [0402]  56.65 52.4 270 top
R265  10.0K, DNI  [0402]  70.75 55.2 90 top
R266  1.00K, DNI  [0402]  2.55 50.62 90 bottom
R267  1.00K  [0402]  2.55 49.74 90 bottom
R268  1.00K, DNI  [0402]  4.2 53.04 0 bottom
R269  1.00K, DNI  [0402]  11.31 53.04 0 bottom
R270  1.00K  [0402]  3.18 53.04 0 bottom
R271  1.00K  [0402]  10.29 53.04 0 bottom
R272  1.00K  [0402]  12.71 48.72 270 bottom
R273  33  [0402]  2.55 47.96 270 bottom
R274  1.00K, DNI  [0402]  12.71 49.74 270 bottom
R275  33  [0402]  2.55 48.85 270 bottom
R276  33  [0402]  5.21 53.04 180 bottom
R277  33  [0402]  6.23 53.04 180 bottom
R278  33  [0402]  8.26 53.04 180 bottom
R279  1.00K  [0402]  11.69 42.88 180 bottom
R280  33  [0402]  9.28 53.04 180 bottom
R281  1.00K  [0402]  12.71 42.88 180 bottom
R282  0  [0402]  2.55 45.29 270 bottom
R283  0  [0402]  2.55 44.4 270 bottom
R284  1.00K, DNI  [0402]  2.55 46.18 90 bottom
R285  1.00K  [0402]  2.55 47.07 90 bottom
R286  1.00K  [0402]  2.55 42.24 90 bottom
R287  1.00K, DNI  [0402]  2.55 43.13 90 bottom
R288  0  [0402]  20.07 32.46 180 bottom
R289  0  [0402]  19.06 32.46 180 bottom
R290  0  [0402]  23.76 32.46 180 bottom
R291  0  [0402]  22.74 32.46 180 bottom
R292  49.9  [0402]  14.87 24.84 270 bottom
R293  1.00K, DNI  [0402]  25.53 34.37 0 bottom
R294  49.9  [0402]  14.87 25.86 270 bottom
R295  1.00K  [0402]  24.65 34.37 0 bottom
R296  49.9, DNI  [0402]  14.87 27.76 270 bottom
R297  49.9, DNI  [0402]  14.87 28.78 270 bottom
R298  1.00K, DNI  [0402]  23.63 21.67 180 bottom
R299  1.00K  [0402]  24.65 21.67 180 bottom
R300  1.00K, DNI  [0402]  21.6 21.67 180 bottom
R301  1.00K  [0402]  22.61 21.67 180 bottom
R302  10.0K  [0402]  250.71 43.51 270 bottom
R303  1.00K  [0402]  20.58 21.67 180 bottom
R304  10.0K  [0402]  250.71 44.78 270 bottom
R305  1.00K  [0402]  19.57 21.67 180 bottom
R306  10.0K  [0402]  250.71 46.05 270 bottom
R307  0  [0402]  244.61 46.05 90 bottom
R308  0  [0402]  244.61 44.78 90 bottom
R309  0  [0402]  244.61 43.51 90 bottom
R310  0  [0402]  25.15 49.86 90 bottom
R311  0  [0402]  25.15 50.88 90 bottom
R312  22  [0402]  25.15 46.18 270 bottom
R313  22  [0402]  25.15 47.2 270 bottom
R314  49.9  [0402]  17.53 55.07 180 bottom
R315  1.00K, DNI  [0402]  25.15 43.39 270 bottom
R316  49.9  [0402]  18.55 55.07 180 bottom
R317  1.00K  [0402]  25.15 42.37 270 bottom
R318  49.9, DNI  [0402]  20.45 55.07 180 bottom
R319  49.9, DNI  [0402]  21.47 55.07 180 bottom
R320  1.00K, DNI  [0402]  14.74 45.67 90 bottom
R321  1.00K  [0402]  14.74 44.66 90 bottom
R322  1.00K, DNI  [0402]  14.74 46.69 90 bottom
R323  1.00K  [0402]  14.74 47.7 90 bottom
R324  1.00K  [0402]  14.74 48.72 90 bottom
R325  1.00K  [0402]  14.74 49.74 90 bottom
R326  10.0K  [0402]  54.19 10.75 270 bottom
R327  33.2  [0402]  59.06 12.4 90 bottom
R328  33.2  [0402]  56.14 15.19 270 bottom
R331  10.0K  [0402]  49.46 10.59 90 bottom
R332  33.2  [0402]  52.08 12.52 90 bottom
R333  33.2  [0402]  49.16 15.32 270 bottom
R334  10.0K  [0402]  47.63 11.38 90 bottom
R337  0  [0402]  63.15 76.18 0 top
R338  0  [0402]  64.17 76.18 0 top
R339  0  [0402]  65.18 76.18 0 top
R340  10.0K  [0402]  64.78 82.63 180 bottom
R341  0  [0402]  66.2 76.18 0 top
R342  0  [0402]  68.49 80.37 90 top
R343  0  [0402]  64.35 84.15 270 bottom
R344  0  [0402]  68.49 81.39 90 top
R345  10.0K  [0402]  93.73 35.77 0 bottom
R346  0  [0402]  87.23 36.88 270 top
R347  0  [0402]  87.23 35.87 270 top
R348  0  [0402]  87.23 34.85 270 top
R349  0  [0402]  87.23 33.84 270 top
R351  0  [0402]  91.42 31.55 0 top
R352  6.81K  [0402]  95.13 34.88 180 bottom
R353  0  [0402]  92.44 31.55 0 top
R358  100  [0402]  214.38 100.15 270 bottom
R359  10.0K  [0402]  167.14 105.62 270 bottom
R366  4.70K  [0402]  193.68 64.47 180 bottom
R367  4.70K  [0402]  192.67 64.47 180 bottom
R368  4.70K, DNI  [0402]  192.67 61.67 0 bottom
R369  4.70K, DNI  [0402]  193.68 61.67 0 bottom
R370  100K  [0402]  195.71 61.67 180 bottom
R376  4.70K, DNI  [0402]  73.54 96.98 270 bottom
R377  4.70K, DNI  [0402]  73.54 95.96 270 bottom
R378  4.70K  [0402]  65.92 95.84 90 bottom
R379  4.70K  [0402]  65.92 96.85 90 bottom
R380  100K  [0402]  65.92 98.5 270 bottom
R381  4.70K  [0402]  65.82 104.63 90 bottom
R382  4.70K  [0402]  65.82 105.64 90 bottom
R383  4.70K  [0402]  73.57 105.74 270 bottom
R384  4.70K  [0402]  73.57 104.88 270 bottom
R385  100K  [0402]  73.67 103.33 90 bottom
R394  2K  [0402]  39.38 108.41 180 bottom
R395  0, DNI  [0402]  41.54 108.41 180 bottom
R398  10.0K  [0402]  17.03 80.09 180 bottom
R399  49.9  [0402]  38.36 108.41 180 bottom
R400  200  [0402]  67.19 28.27 90 top
R401  200  [0402]  67.19 24.46 90 top
R402  200  [0402]  53.73 48.21 270 top
R403  200  [0402]  53.73 45.16 270 top
R404  56.2  [0402]  240.16 105.11 90 bottom
R405  56.2  [0402]  238.13 107.27 90 bottom
R406  56.2  [0402]  235.59 107.27 90 bottom
R407  56.2  [0402]  232.29 107.27 90 bottom
R411  56.2  [0402]  27.95 107.39 0 bottom
R417  49.9, DNI  [2512]  32.65 108.28 0 bottom
R418  1.00K  [0402]  211.97 106 0 bottom
R422  1.00K  [0402]  217.24 105.97 0 bottom
R425  1.00K  [0402]  216.22 105.97 0 bottom
R426  1M  [0402]  242.58 105.11 270 bottom
R427  1.00K  [0402]  220.54 105.97 0 bottom
R428  1.00K, DNI  [0402]  224.81 106 0 bottom
R429  10.0K  [0402]  222.41 56.52 270 bottom
R430  10.0K  [0402]  222.41 58.55 270 bottom
R431  10.0K  [0402]  222.41 61.6 270 bottom
R432  10.0K  [0402]  28.33 86.44 90 bottom
R433  10.0K  [0402]  28.33 88.09 90 bottom
R434  10.0K  [0402]  37.35 80.72 270 bottom
R435  10.0K, DNI  [0402]  222.41 57.53 90 bottom
R436  10.0K, DNI  [0402]  222.41 59.57 90 bottom
R437  10.0K, DNI  [0402]  222.41 60.58 90 bottom
R438  10.0K  [0402]  224.44 59.31 90 bottom
R439  10.0K  [0402]  34.42 31.83 270 bottom
R440  10.0K  [0402]  34.42 33.1 270 bottom
R441  10.0K, DNI  [0402]  27.31 35.13 0 bottom
R442  10.0K  [0402]  30.61 25.35 270 bottom
R443  10.0K, DNI  [0402]  34.42 30.81 90 bottom
R444  10.0K, DNI  [0402]  34.42 34.11 90 bottom
R445  10.0K  [0402]  26.42 35.13 180 bottom
R446  10.0K, DNI  [0402]  22.61 96.25 0 bottom
R447  10.0K  [0402]  23.63 96.25 0 bottom
R448  20.0K  [0402]  19.39 96.54 0 bottom
R449  100K  [0402]  21.55 97.11 180 bottom
R450  0, DNI  [0402]  7.5 94.31 90 bottom
R451  2K  [0402]  13.09 88.79 0 bottom
R452  2K  [0402]  13.98 88.79 0 bottom
R453  0  [0402]  7.37 97.97 270 bottom
R454  22  [0402]  11.56 89.8 180 top
R455  10.0K  [0402]  231.27 42.5 270 top
R456  41.2K  [0402]  228.06 44.02 270 bottom
R457  10.0K  [0402]  231.27 41.48 270 top
R458  5.76K  [0402]  228.06 43 90 bottom
R459  10.0K  [0402]  231.27 45.54 90 top
R460  10.0K  [0402]  231.27 40.46 90 top
R461  3.16K  [0402]  231.27 44.53 270 top
R462  174K  [0402]  231.27 43.51 270 top
R463  13K  [0402]  228.99 47.96 0 bottom
R464  41.2K  [0402]  245.24 93.42 270 bottom
R465  5.76K  [0402]  247.28 93.42 90 bottom
R466  41.2K  [0402]  249.31 93.42 270 bottom
R467  10  [0402]  220.61 78.56 180 top
R468  100K  [0402]  213.49 79.58 0 bottom
R469  240  [0402]  219.21 81.49 0 bottom
R470  1.00K  [0402]  210.51 79.9 90 top
R471  10.0K  [0402]  223.32 81.78 90 top
R472  41.2K, DNI  [0402]  226.83 82.25 90 bottom
R473  49.9, DNI  [0402]  242.2 71.2 270 top
R474  10.0K  [0402]  223.32 82.8 90 top
R475  5.76K, DNI  [0402]  225.81 80.18 90 bottom
R476  10.0K  [0402]  223.32 78.77 270 top
R477  1.78K  [0402]  223.32 79.77 90 top
R478  10.0K  [0402]  223.32 83.81 270 top
R479  174K  [0402]  223.32 80.72 90 top
R480  13K  [0402]  225.56 76.41 180 bottom
R494  10.0K, DNI  [0402]  31 102.95 270 bottom
R495  10.0K, DNI  [0402]  33.54 105.23 180 bottom
R496  10.0K, DNI  [0402]  15.63 60.28 0 bottom
R497  4.02K  [0402]  34.42 99.58 0 top
R498  2.61K  [0402]  32.39 98.69 180 bottom
R499  2.61K  [0402]  19.06 64.34 0 bottom
R500  1K  [0402]  34.42 101.49 180 top
R501  1K  [0402]  32.65 102.63 0 bottom
R502  1.87K  [0402]  17.91 63.39 180 bottom
R503  10.0K  [0402]  26.17 107.39 180 bottom
R504  0  [0402]  31 103.84 90 bottom
R505  0  [0402]  32.52 105.23 0 bottom
R506  0  [0402]  16.64 60.28 180 bottom
R507  0  [0402]  27.06 107.39 180 bottom
R522  0, DNI  [0402]  26.17 109.17 180 bottom
R523  10.0K  [0402]  18.55 108.66 270 bottom
R524  0, DNI  [0402]  27.06 109.17 0 bottom
R525  10.0K, DNI  [0402]  20.58 109.55 270 bottom
R526  0, DNI  [0402]  18.55 109.55 270 bottom
R527  0  [0402]  20.58 108.66 90 bottom
R528  0  [0402]  27.95 109.17 0 bottom
R529  0  [0402]  238.64 37.29 90 top
R530  0  [0402]  236.48 37.29 90 top
R531  1  [0603]  181.32 61.62 0 top
R532  100  [0402]  129.93 72.72 90 bottom
R533  0  [0402]  131.96 72.72 90 bottom
R534  0  [0402]  131.96 71.83 90 bottom
R535  10.0K, DNI  [0402]  186.82 52.15 270 top
R536  10.0K  [0402]  186.82 49.48 270 top
R537  4.99k  [0402]  183.9 58.24 180 top
R538  4.70K, DNI  [0402]  186.82 48.59 90 top
R539  4.70K, DNI  [0402]  186.82 47.7 90 top
R540  2K  [0402]  185.43 46.43 180 top
R541  100  [0402]  129.93 71.83 270 bottom
R542  0  [0402]  186.82 53.04 90 top
R543  10.0K, DNI  [0402]  171.71 58.5 270 top
R544  0  [0402]  171.71 54.43 90 top
R545  0  [0402]  172.47 53.67 270 bottom
R546  0  [0402]  172.47 55.2 270 bottom
R547  10.0K, DNI  [0402]  171.71 57.48 90 top
R548  0  [0402]  178.19 46.43 0 top
R549  0  [0402]  172.94 60.53 180 top
R550  3.74K  [0402]  186.82 54.82 90 top
R551  3.74K  [0402]  186.82 55.7 90 top
R552  4.42K  [0402]  186.82 56.59 90 top
R553  3.09K  [0402]  186.82 57.48 90 top
R554  18.7k  [0402]  186.82 53.93 270 top
R555  6.49K  [0402]  186.82 58.37 270 top
R556  0  [0402]  181.87 46.43 0 top
R557  10.0K, DNI  [0402]  184.54 46.43 180 top
R558  10.0K, DNI  [0402]  182.76 46.43 180 top
R559  0  [0402]  183.65 46.43 0 top
R560  10.0K, DNI  [0402]  186.82 51.26 270 top
R561  0  [0402]  178.32 60.53 180 top
R562  10.0K  [0402]  179.2 60.53 0 top
R563  10.0K, DNI  [0402]  180.98 46.43 180 top
R564  10.0K, DNI  [0402]  175.65 60.53 0 top
R565  0  [0402]  176.54 60.53 180 top
R566  10.0K  [0402]  177.43 60.53 0 top
R567  0, DNI  [0402]  161.93 45.04 270 top
R568  0, DNI  [0402]  161.93 44.02 270 top
R569  1  [0603]  162.57 40.85 90 top
R570  10.0K  [0402]  161.93 46.05 270 top
R571  10.0K  [0402]  161.93 43 270 top
R572  10.0K, DNI  [0402]  162.38 42.37 90 bottom
R573  499  [0402]  160.92 43.26 0 bottom
R574  0  [0402]  160.92 45.16 0 bottom
R575  0, DNI  [0402]  161.93 59.51 270 top
R576  0, DNI  [0402]  161.93 58.5 270 top
R577  1  [0603]  162.57 55.32 90 top
R578  10.0K  [0402]  161.93 60.53 270 top
R579  10.0K  [0402]  161.93 57.48 270 top
R580  10.0K, DNI  [0402]  162.38 56.85 90 bottom
R581  499  [0402]  160.92 57.74 0 bottom
R582  0  [0402]  160.92 59.64 0 bottom
R583  0, DNI  [0402]  161.93 73.99 270 top
R584  0, DNI  [0402]  161.93 72.98 270 top
R585  1  [0603]  162.57 69.8 90 top
R586  10.0K  [0402]  161.93 75.01 270 top
R587  10.0K  [0402]  161.93 71.96 270 top
R588  10.0K, DNI  [0402]  162.38 71.33 90 bottom
R589  499  [0402]  160.92 72.21 0 bottom
R590  0  [0402]  160.92 74.12 0 bottom
R591  0, DNI  [0402]  161.93 88.47 270 top
R592  0, DNI  [0402]  161.93 87.45 270 top
R593  1  [0603]  162.57 84.28 90 top
R594  10.0K  [0402]  161.93 89.36 270 top
R595  10.0K  [0402]  161.93 86.44 270 top
R596  10.0K, DNI  [0402]  162.38 85.8 90 bottom
R597  499  [0402]  160.92 86.69 0 bottom
R598  0  [0402]  160.92 88.6 0 bottom
R599  0, DNI  [0402]  161.93 30.43 270 top
R600  0, DNI  [0402]  161.93 29.42 270 top
R601  1  [0603]  162.57 26.24 90 top
R602  10.0K  [0402]  161.93 31.45 270 top
R603  10.0K  [0402]  161.93 28.4 270 top
R604  10.0K, DNI  [0402]  162.38 27.76 90 bottom
R605  499  [0402]  160.92 28.65 0 bottom
R606  0  [0402]  160.92 30.56 0 bottom
R609  0, DNI  [0402]  64.9 67.39 270 bottom
R614  0, DNI  [0402]  63.13 67.52 270 bottom
R620  0  [0402]  64.02 66.5 270 bottom
R637  0  [0402]  44.46 92.53 270 bottom
R641  10.0K  [0402]  177.3 46.43 180 bottom
R642  0  [0402]  180.47 46.94 90 bottom
R643  0  [0402]  175.14 60.15 90 bottom
R644  0  [0402]  62.49 72.98 90 bottom
R645  0  [0402]  55.38 92.66 270 bottom
R663  10.0K, DNI  [0402]  207.14 34.88 0 bottom
R664  10.0K  [0402]  204.35 34.88 0 bottom
R665  0  [0402]  200.41 72.72 180 bottom
R666  1K  [0402]  205.24 36.97 0 top
R667  0  [0402]  206.13 34.88 180 bottom
R668  1K  [0402]  206.13 36.08 0 top
R704  10.0K, DNI  [0402]  197.37 34.88 0 bottom
R706  2.61K  [0402]  195.46 36.97 180 top
R708  1K  [0402]  196.35 36.08 0 top
R709  10.0K  [0402]  196.35 32.46 180 bottom
R711  0  [0402]  196.35 34.88 180 bottom
R712  0  [0402]  198.38 32.46 0 bottom
R713  0  [0402]  197.37 32.46 0 bottom
R714  0  [0402]  199.4 32.46 0 bottom
R715  4.02K  [0402]  186.95 92.73 180 top
R716  4.02K  [0402]  143.07 16.33 270 top
R717  10.0K  [0402]  194.06 92.28 180 bottom
R718  10.0K  [0402]  144.28 21.8 270 bottom
R719  1K  [0402]  187.84 91.84 0 top
R720  1K  [0402]  144.85 16.33 90 top
R721  10.0K  [0402]  195.08 104.47 180 top
R722  10.0K  [0402]  67.95 13.92 90 top
R723  10.0K  [0402]  194.06 102.57 0 top
R724  10.0K  [0402]  66.05 14.94 270 top
R725  10.0K, DNI  [0402]  189.87 98 270 bottom
R726  0  [0402]  188.86 90.63 180 bottom
R727  0  [0402]  145.93 17.35 270 bottom
R728  0  [0402]  190.89 98 270 top
R729  0  [0402]  61.48 17.1 180 bottom
R737  10.0K  [0402]  164.85 105.62 270 bottom
R738  10.0K  [0402]  72.91 78.95 90 bottom
R739  10.0K  [0402]  70.75 56.09 270 top
R740  10.0K  [0402]  250.71 52.4 90 bottom
R741  10.0K, DNI  [0402]  62.49 71.83 270 bottom
R742  2.61K  [0402]  65.35 72.85 90 top
R743  3.24K  [0402]  63.57 72.85 270 top
R744  10.0K  [0402]  63.13 63.83 270 bottom
R745  2.61K  [0402]  65.35 64.98 90 top
R746  1K  [0402]  63.57 64.98 270 top
R747  100, DNI  [0402]  61.86 43.26 90 top
R748  100, DNI  [0402]  64.78 56.09 90 top
R749  100, DNI  [0402]  68.84 56.09 90 top
R750  100, DNI  [0402]  66.81 56.09 90 top
R753  49.9, DNI  [0402]  8.26 54.82 180 bottom
R754  49.9, DNI  [0402]  9.28 54.82 180 bottom
R755  49.9, DNI  [0402]  75.51 60.7 90 bottom
R756  49.9, DNI  [0402]  75.51 61.59 90 bottom
R757  49.9, DNI  [0402]  71.44 63.32 90 bottom
R758  49.9, DNI  [0402]  71.44 62.44 90 bottom
R759  10.0K  [0402]  68.35 75.36 90 bottom
R760  10.0K  [0402]  68.35 74.36 90 bottom
R761  1.00K  [0402]  88.1 71.14 0 bottom
R762  4.70K  [0402]  89.29 68.91 60 bottom
R763  10.0K,DNI  [0402]  73.03 77.93 90 bottom
R764  10.0K  [0402]  68.35 77.36 90 bottom
R765  10.0K  [0402]  250.71 53.67 90 bottom
R766  1.00K  [0402]  229.13 106 0 bottom
R767  1.00K  [0402]  228.11 106 0 bottom
R768  10.0K  [0402]  23.18 85.03 0 bottom
R769  10.0K  [0402]  36.39 54.43 270 bottom
R770  10.0K  [0402]  32.52 92.28 270 bottom
R771  10.0K  [0402]  24.9 92.28 270 bottom
R772  10.0K  [0402]  33.92 59.13 0 bottom
R773  10.0K  [0402]  34.93 59.13 0 bottom
R774  0  [0402]  74.18 10.37 90 top
R777  1.00K  [0402]  212.99 106 0 bottom
R780  10.0K  [0402]  37.47 107.52 0 bottom
R784  51.1K, DNI  [0402]  41.03 40.21 90 bottom
R785  51.1K  [0402]  41.03 41.23 90 bottom
R786  10.0K  [0402]  39.33 65.1 0 bottom
R789  10.0K  [0402]  26.3 62.69 90 bottom
R808  10.0K  [0402]  214.38 101.17 270 bottom
R814  51.1K, DNI  [0402]  209.3 103.08 90 bottom
R815  51.1K  [0402]  216.8 103.08 270 bottom
R816  51.1K  [0402]  216.8 102.06 270 bottom
R817  51.1K  [0402]  216.8 101.04 270 bottom
R818  51.1K  [0402]  216.8 100.03 270 bottom
R819  51.1K  [0402]  209.3 100.03 90 bottom
R820  51.1K  [0402]  209.3 101.04 90 bottom
R821  51.1K  [0402]  209.3 102.06 90 bottom
R822  51.1K  [0402]  222.13 100.03 90 bottom
R823  51.1K  [0402]  222.13 101.04 90 bottom
R824  51.1K  [0402]  222.13 102.06 90 bottom
R825  51.1K  [0402]  222.13 103.08 90 bottom
R833  51.1K  [0402]  5.6 22.43 270 bottom
R834  51.1K  [0402]  5.6 23.45 270 bottom
R836  51.1K  [0402]  5.6 28.65 270 bottom
R837  51.1K  [0402]  5.6 29.67 270 bottom
R839  10.0K  [0402]  53.41 96.47 90 bottom
R840  10.0K  [0402]  53.41 97.61 90 bottom
R841  10.0K  [0402]  130.56 74.5 270 bottom
R842  100, DNI  [0402]  62.62 56.09 90 top
R843  100, DNI  [0402]  60.59 56.09 90 top
R845  33.2  [0402]  75.19 46.43 90 bottom
R847  1.00K  [0402]  26.93 97.36 180 top
R848  10.0K  [0402]  39.12 65.48 90 top
R849  10.0K  [0402]  39.13 64.32 90 top
R852  0  [0402]  49.92 92.92 90 bottom
R854  10.0K  [0402]  45.85 92.97 180 bottom
R855  10.0K  [0402]  46.74 92.97 180 bottom
R856  4.99k  [0402]  49.11 91.52 135 bottom
R857  11.3K  [0402]  42.43 90.76 90 bottom
R858  5.76K  [0402]  44.46 89.87 90 bottom
R862  10.0K  [0402]  196.86 59.01 0 bottom
R863  34.8K  [0402]  193.17 55.96 270 bottom
R864  10.0K  [0402]  193.17 57.2 90 bottom
R865  54.9K  [0402]  195.59 59.01 180 bottom
R866  DNI  [0402]  197.48 57.23 90 bottom
R868  8.06K  [0402]  190.76 56.66 0 top
R869  10.0K, DNI  [0402]  179.39 31.96 90 bottom
R1004  13.3K  [0402]  180.88 36.27 180 bottom
R1005  10.0K  [0402]  181.11 29.03 315 bottom
R1006  1  [0603]  51.57 86.44 180 bottom
R1007  10.0K  [0402]  47.63 92.97 0 bottom
R1008  7.32K  [0402]  42.43 92.53 270 bottom
R6791  20.0K  [0402]  44.46 88.98 90 bottom
R6794  24.9K  [0402]  44.46 90.76 90 bottom
R6797  24.9K  [0402]  42.43 91.65 90 bottom
R6798  24.9K  [0402]  42.43 93.42 90 bottom
R6799  11K  [0402]  44.46 88.09 90 bottom
R6802  1  [0603]  194.19 76.53 90 bottom
R6807  10.0K  [0402]  200.72 80.47 270 bottom
R6808  0  [0402]  200.29 83.64 180 bottom
R6809  0  [0402]  200.72 77.93 90 bottom
R6810  4.99k  [0402]  199.27 79 45 bottom
R6811  10.0K  [0402]  200.72 81.36 90 bottom
R6812  24.9K  [0402]  198.51 83.64 0 bottom
R6813  24.9K  [0402]  199.4 85.68 0 bottom
R6814  16.2K  [0402]  201.18 85.68 0 bottom
R6815  20.0K  [0402]  196.73 83.64 0 bottom
R6818  10.0K  [0402]  200.72 82.25 90 bottom
R6819  7.32K  [0402]  197.62 83.64 180 bottom
R6821  11.3K  [0402]  198.51 85.68 0 bottom
R6822  11K  [0402]  195.84 83.64 0 bottom
R6825  10.0K  [0402]  195.84 85.68 0 bottom
R6828  0, DNI  [0402]  198.13 80.6 180 bottom
R6829  0, DNI  [0402]  200.72 79.58 90 bottom
R6830  0, DNI  [0402]  201.18 83.64 0 bottom
R6831  0, DNI  [0402]  199.4 83.64 180 bottom
R6832  17.4K  [0402]  200.29 85.68 180 bottom
R6833  0, DNI  [0402]  44.46 93.42 90 bottom
R6834  0, DNI  [0402]  47.63 90.38 270 bottom
R6835  0, DNI  [0402]  44.46 91.65 270 bottom
R6836  0, DNI  [0402]  48.52 92.97 180 bottom
R6837  22  [0402]  70.49 46.81 270 top
R6838  DNI  [0402]  192.03 59.01 180 bottom
R6839  10  [0402]  199.27 54.69 270 bottom
R6840  DNI  [0402]  109.78 74.47 330 bottom
R6841  DNI  [0402]  108.62 75.13 330 bottom
R6842  0  [0402]  75.65 74.5 270 bottom
R6843  0  [0402]  75.65 73.61 270 bottom
R6844  4.99k  [0402]  42.43 88.09 90 bottom
R6845  24.9K  [0402]  42.43 89.87 90 bottom
R6846  5.76K  [0402]  42.43 88.98 90 bottom
R6847  24.9K  [0402]  40.33 88.98 90 bottom
R6848  11.3K  [0402]  40.33 88.09 90 bottom
R6849  0  [0402]  55.38 91.65 270 bottom
R6850  0  [0402]  54.36 87.45 180 bottom
R6851  13.7K  [0402]  59.7 75.68 180 top
R6852  0  [0402]  58.3 75.17 270 top
R6853  499  [0402]  58.3 76.19 270 top
R6855  0  [0402]  42.3 75.17 90 top
R6857  10  [0402]  91.96 48.4 0 bottom
R6858  10  [0402]  90.94 48.4 180 bottom
R6859  10  [0402]  103 48.34 0 bottom
R6860  10  [0402]  101.99 48.34 180 bottom
R6861  536  [0402]  183.56 70.82 180 top
R6862  0  [0402]  182.54 70.82 180 top
R6863  28K  [0402]  183.05 69.42 90 top
R6865  0  [0402]  181.4 86.69 0 top
R6867  0  [0402]  199.4 72.72 180 bottom
R6868  0  [0402]  195.21 73.74 90 bottom
R6869  10  [0402]  96.53 48.4 0 bottom
R6870  10  [0402]  97.42 48.4 180 bottom
R6871  10  [0402]  106.18 48.34 0 bottom
R6872  10  [0402]  105.16 48.34 180 bottom
R6873  24.9K  [0402]  197.62 85.68 0 bottom
R6874  5.76K  [0402]  196.73 85.68 0 bottom
R6875  24.9K  [0402]  196.73 87.77 0 bottom
R6876  11.3K  [0402]  195.84 87.77 0 bottom
R6877  DNI  [0402]  190.76 54.88 180 top
R6878  10  [0402]  22.87 66.37 0 bottom
R6879  10  [0402]  21.98 66.37 0 bottom
R6880  174K  [0402]  182.32 37.04 270 bottom
R6881  0  [0402]  198.89 95.52 180 top
R6882  0  [0402]  200.03 95.52 180 top
R6883  649  [0402]  42.3 76.19 90 top
R6884  1.74K  [0402]  40.9 75.68 180 top
R6885  698  [0402]  182.42 86.69 0 top
R6886  11K  [0402]  181.91 88.09 270 top
R6887  10.0K  [0402]  33.54 64.47 270 top
R6888  56.2  [0402]  37.22 65.48 90 top
R6889  10.0K  [0402]  23.5 62.18 180 top
R6890  56.2  [0402]  30.36 64.72 90 top
R6891  10.0K  [0402]  30.92 15.37 180 bottom
